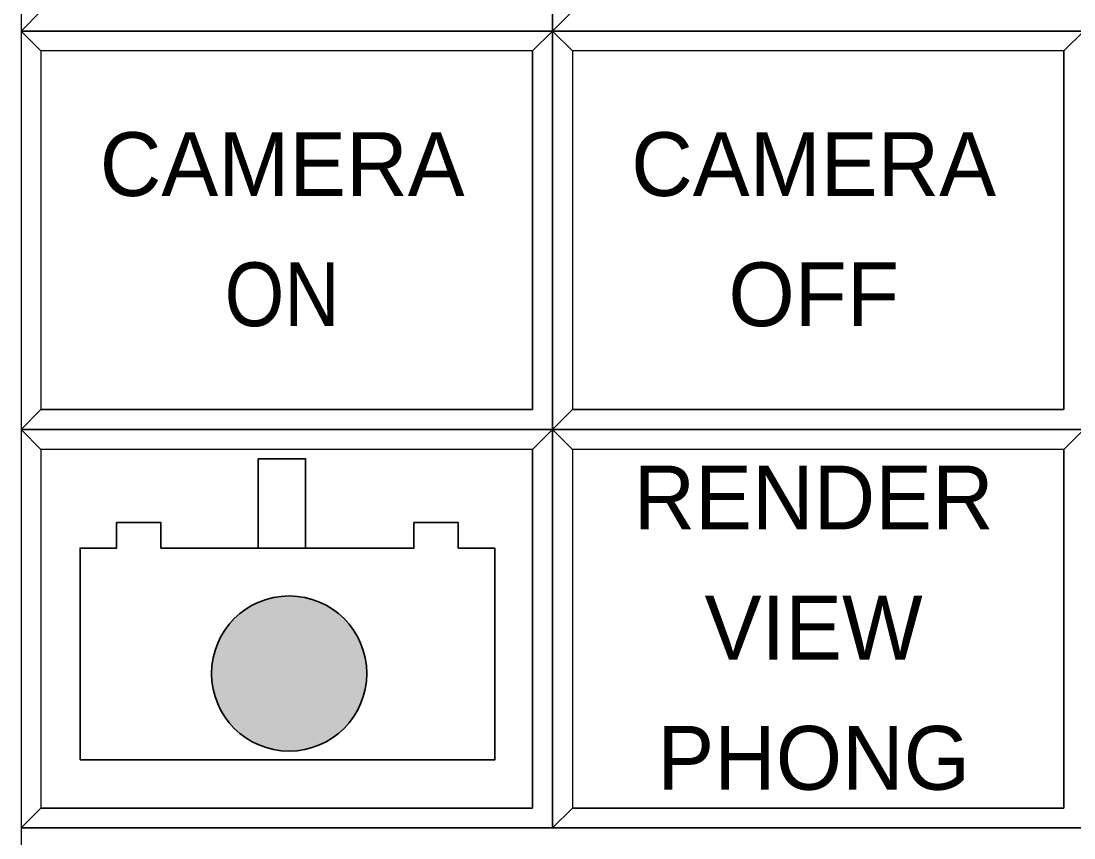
# Model space of a CAD drawing. Extents: x 95906.9 to 95918.9, y 90964.8 to 90972.9.
# Drawn here: x 95914.53 to 95915.322, y 90965.554 to 90966.169 of the extents above; entities that cross this region are included whole.
import ezdxf
from ezdxf.enums import TextEntityAlignment as Align

# ---------------------------------------------------------------- set-up
doc = ezdxf.new("R2010")
doc.units = 0
doc.header["$LTSCALE"] = 0.019
for name, color, linetype, lineweight in [('1', 7, 'Continuous', 25), ('11', 7, 'Continuous', 25), ('2', 7, 'Continuous', 13), ('3', 7, 'Continuous', 25), ('4', 7, 'Continuous', 35), ('6', 7, 'Continuous', 35)]:
    doc.layers.add(name, color=color, linetype=linetype, lineweight=lineweight)

msp = doc.modelspace()

# ---------------------------------------------------------------- hatches: boundary and pattern name
at = {"layer": '6'}
msp.add_hatch(color=256, dxfattribs=at).paths.add_polyline_path([(95914.79, 90965.678, 1), (95914.6732, 90965.678, 1)])

# ---------------------------------------------------------------- linework, layer by layer
at = {"layer": '1'}
for points in [[(95914.5298, 90966.1617), (95914.9298, 90966.1617), (95914.9298, 90966.4617), (95914.5298, 90966.4617)], [(95914.9298, 90966.1617), (95915.3298, 90966.1617), (95915.3298, 90966.4617), (95914.9298, 90966.4617)], [(95914.5298, 90965.8617), (95914.9298, 90965.8617), (95914.9298, 90966.1617), (95914.5298, 90966.1617)], [(95914.9298, 90965.8617), (95915.3298, 90965.8617), (95915.3298, 90966.1617), (95914.9298, 90966.1617)], [(95914.5298, 90965.5617), (95914.9298, 90965.5617), (95914.9298, 90965.8617), (95914.5298, 90965.8617)], [(95914.9298, 90965.5617), (95915.3298, 90965.5617), (95915.3298, 90965.8617), (95914.9298, 90965.8617)], [(95914.5298, 90965.4617), (95916.1298, 90965.4617), (95916.1298, 90965.5617), (95914.5298, 90965.5617)]]:
    msp.add_lwpolyline(points, close=True, dxfattribs=at)
at = {"layer": '11'}
for points in [[(95914.5448, 90965.8767), (95914.9148, 90965.8767), (95914.9148, 90966.1467), (95914.5448, 90966.1467)], [(95914.9448, 90965.8767), (95915.3148, 90965.8767), (95915.3148, 90966.1467), (95914.9448, 90966.1467)], [(95914.5448, 90965.5767), (95914.9148, 90965.5767), (95914.9148, 90965.8467), (95914.5448, 90965.8467)], [(95914.9448, 90965.5767), (95915.3148, 90965.5767), (95915.3148, 90965.8467), (95914.9448, 90965.8467)]]:
    msp.add_lwpolyline(points, close=True, dxfattribs=at)
at = {"layer": '2'}
for points in [[(95914.5298, 90966.4617), (95914.5298, 90966.1617), (95914.5448, 90966.1767), (95914.5448, 90966.4467), (95914.9148, 90966.4467), (95914.9298, 90966.4617)], [(95914.9298, 90966.4617), (95914.9298, 90966.1617), (95914.9448, 90966.1767), (95914.9448, 90966.4467), (95915.3148, 90966.4467), (95915.3298, 90966.4617)], [(95914.5298, 90966.1617), (95914.5298, 90965.8617), (95914.5448, 90965.8767), (95914.5448, 90966.1467), (95914.9148, 90966.1467), (95914.9298, 90966.1617)], [(95914.9298, 90966.1617), (95914.9298, 90965.8617), (95914.9448, 90965.8767), (95914.9448, 90966.1467), (95915.3148, 90966.1467), (95915.3298, 90966.1617)], [(95914.5298, 90965.8617), (95914.5298, 90965.5617), (95914.5448, 90965.5767), (95914.5448, 90965.8467), (95914.9148, 90965.8467), (95914.9298, 90965.8617)], [(95914.9298, 90965.8617), (95914.9298, 90965.5617), (95914.9448, 90965.5767), (95914.9448, 90965.8467), (95915.3148, 90965.8467), (95915.3298, 90965.8617)], [(95914.5298, 90965.5617), (95914.5298, 90965.4617), (95914.5448, 90965.4767), (95914.5448, 90965.5467), (95916.1148, 90965.5467), (95916.1298, 90965.5617)]]:
    msp.add_lwpolyline(points, close=True, dxfattribs=at)
at = {"layer": '3'}
for points in [[(95914.5298, 90966.1617), (95914.9298, 90966.1617), (95914.9298, 90966.4617), (95914.9148, 90966.4467), (95914.9148, 90966.1767), (95914.5448, 90966.1767)], [(95914.9298, 90966.1617), (95915.3298, 90966.1617), (95915.3298, 90966.4617), (95915.3148, 90966.4467), (95915.3148, 90966.1767), (95914.9448, 90966.1767)], [(95914.5298, 90965.8617), (95914.9298, 90965.8617), (95914.9298, 90966.1617), (95914.9148, 90966.1467), (95914.9148, 90965.8767), (95914.5448, 90965.8767)], [(95914.9298, 90965.8617), (95915.3298, 90965.8617), (95915.3298, 90966.1617), (95915.3148, 90966.1467), (95915.3148, 90965.8767), (95914.9448, 90965.8767)], [(95914.5298, 90965.5617), (95914.9298, 90965.5617), (95914.9298, 90965.8617), (95914.9148, 90965.8467), (95914.9148, 90965.5767), (95914.5448, 90965.5767)], [(95914.9298, 90965.5617), (95915.3298, 90965.5617), (95915.3298, 90965.8617), (95915.3148, 90965.8467), (95915.3148, 90965.5767), (95914.9448, 90965.5767)]]:
    msp.add_lwpolyline(points, close=True, dxfattribs=at)
at = {"layer": '4'}
for p, q in [((95914.5448, 90966.1467), (95914.5298, 90966.1617)), ((95914.9448, 90966.1467), (95914.9298, 90966.1617)), ((95914.5448, 90965.8467), (95914.5298, 90965.8617)), ((95914.9448, 90965.8467), (95914.9298, 90965.8617))]:
    msp.add_line(p, q, dxfattribs=at)
at = {"layer": '6'}
for points in [[(95914.7083, 90965.7723), (95914.744, 90965.7723), (95914.744, 90965.8397), (95914.7083, 90965.8397)], [(95914.5742, 90965.6129), (95914.8864, 90965.6129), (95914.8864, 90965.7724), (95914.8589, 90965.7724), (95914.8589, 90965.7916), (95914.8255, 90965.7916), (95914.8255, 90965.7724), (95914.6351, 90965.7724), (95914.6351, 90965.7916), (95914.6017, 90965.7916), (95914.6017, 90965.7724), (95914.5742, 90965.7724)]]:
    msp.add_lwpolyline(points, close=True, dxfattribs=at)
msp.add_circle((95914.7316, 90965.678), 0.0584, dxfattribs=at)

# ---------------------------------------------------------------- texts
for s, p in [('CAMERA', (95914.72635, 90966.0375)), ('CAMERA', (95915.12635, 90966.0375)), ('OFF', (95915.1264, 90965.9395)), ('RENDER', (95915.12635, 90965.7865)), ('VIEW', (95915.12635, 90965.6885)), ('PHONG', (95915.1264, 90965.5905))]:
    msp.add_text(s, height=0.048, dxfattribs=at).set_placement(p, align=Align.CENTER)
at = {"layer": '6', "width": 0.9}
msp.add_text('ON', height=0.048, dxfattribs=at).set_placement((95914.72635, 90965.9395), align=Align.CENTER)

doc.saveas('drawing.dxf')
